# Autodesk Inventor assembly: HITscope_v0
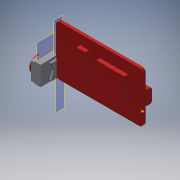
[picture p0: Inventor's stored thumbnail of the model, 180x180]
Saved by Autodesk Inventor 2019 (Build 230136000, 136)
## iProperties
Created: 2021-09
Part Number: HITscope_v0
Material: Generisch
Document SubType Name: Assembly
Designer: Muriel
Author: Muriel
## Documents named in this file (3)
- C:\Users\Muriel\Documents\Inventor\HITscope\HITscope_v0.iam
- C:\Users\Muriel\Documents\Inventor\HITscope\00_ESP32_Board.ipt
- C:\Users\Muriel\Documents\Inventor\HITscope\01_Camera_Module_v0.ipt
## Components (2 placed, 2 different names)
1. 00_ESP32_Board:1 — Fluchtend:1
2. 01_Camera_Module_v0:1 — Fluchtend:1
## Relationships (1: Flush 1)
- Fluchtend:1 [Flush]: 00_ESP32_Board:1 ↔ 01_Camera_Module_v0:1
